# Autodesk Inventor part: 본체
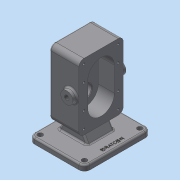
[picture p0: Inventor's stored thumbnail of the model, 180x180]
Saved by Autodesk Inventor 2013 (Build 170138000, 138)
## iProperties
Created: 2020-04
Part Number: 본체
Material: 일반
Document SubType Name: Modeling
Designer: dgall
Density: 1 g/cm^3
Author: dgall
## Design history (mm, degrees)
sketch "스케치1"
  geometry: L1 (-50, 60)-(50, 60); L2 (50, 60)-(50, -60); L3 (50, -60)-(-50, -60); L4 (-50, -60)-(-50, 60); 3 further points
  constraints: 8 end point, 2 midpoint, 2 parallel, 1 horizontal, 1 horizontal alignment, 1 perpendicular, 1 vertical alignment
  dimensions: "d0" = 100 distance of L1.start L1.end; "d2" = 120 distance of L1.end L2.end
extrude "돌출1" new body sketch "스케치1" stored distance "d3" = 10; taper "d4" = 0 deg
node "작업 평면1"
sketch "스케치2"
  geometry: L1 (145, -20)-(25, -20); L2 (25, -20)-(25, -100); L3 (25, -100)-(145, -100); L4 (145, -100)-(145, -20); L5 (-5, -120)-(-5, 0) reference; 2 further points
  constraints: 8 end point, 2 parallel, 1 horizontal, 1 horizontal alignment, 1 midpoint, 1 perpendicular
  dimensions: "d5" = 150 distance between parallel lines of L5 L4; "d6" = 80 distance of L3.end L1.start; "d7" = 120 distance of L1.start L1.end
extrude "돌출2" join sketch "스케치2" distance "d8" = 70; taper "d9" = 0 deg
extrude "돌출3" cut sketch "스케치2" distance "d10" = 17; taper "d11" = 0 deg
sketch "스케치3" dims "d31" = 10, "d38" = 10
  geometry: L1 (-25, -20)-(-145, -20) reference; L2 (-145, -20)-(-145, -100) reference; L3 (-145, -100)-(-25, -100) reference; L4 (-63, -84)-(-107, -84); L5 (-63, -36)-(-107, -36); A1 r 24 centre (-107, -60) between (-107, -36) and (-107, -84); A2 r 24 centre (-63, -60) between (-63, -84) and (-63, -36); 11 further points
  constraints: 4 end point, 4 point on circle, 3 horizontal, 2 centre point, 2 horizontal alignment, 2 midpoint, 2 parallel, 2 tangent, 1 equal radius, 1 vertical, 7 other
  dimensions: "d12" = 48 diameter of A1; "d14" = 44 distance of A2.centre A1.centre; "d15" = 9 distance from line of L2 point (-136, -91); "d16" = 9 distance from line of L3 point (-136, -91); "d17" = 29 horizontal distance of A1.centre point (-136, -91); "d20" = 62 distance of point (-136, -91) point (-136, -29); "d23" = 29 distance of point (-136, -91) point (-107, -91); "d28" = 44 distance of point (-107, -91) point (-63, -91); "d35" = 102 distance of point (-136, -91) point (-34, -91)
extrude "돌출4" cut sketch "스케치3" distance "d40" = 29; taper "d41" = 0 deg
hole "구멍1" sketch "스케치3" diameter "d42" = 4.134; stored, may be unused: countersink angle "d46" = 90 deg, drill point angle "d48" = 118 deg; dims "d43" = 10, "d44" = 4, "d45" = 2, "d47" = 12
sketch "스케치4"
  geometry: C1 r 19 at (-107, -60); A1 r 24 centre (-107, -60) between (-107, -36) and (-107, -84) reference; 1 further point
  constraints: 1 centre point, 1 coincident
  dimensions: "d49" = 38 diameter of C1
extrude "돌출5" join sketch "스케치4" distance "d51" = 41; taper "d52" = 0 deg
hole "구멍2" diameter "d55" = 28; stored, may be unused: countersink angle "d59" = 90 deg, drill point angle "d61" = 0 deg; dims "d53" = 10, "d54" = 10, "d56" = 10, "d57" = 28, "d58" = 7.3, "d60" = 7.3
sketch "스케치5"
  geometry: A1 r 24 centre (-107, -60) between (-107, -36) and (-107, -84) reference; 1 further point
hole "구멍3" sketch "스케치5" at (-107, -60) diameter "d62" = 17; stored, may be unused: countersink angle "d66" = 90 deg, drill point angle "d68" = 0 deg; dims "d63" = 10, "d64" = 25, "d65" = 15, "d67" = 50
sketch "스케치6"
  geometry: A1 r 24 centre (-63, -60) between (-63, -84) and (-63, -36) reference; 1 further point
hole "구멍4" sketch "스케치6" at (-63, -60) diameter "d69" = 25; stored, may be unused: countersink angle "d73" = 90 deg, drill point angle "d75" = 0 deg; dims "d70" = 10, "d71" = 25, "d72" = 15, "d74" = 15
sketch "스케치7"
  geometry: L1 (0, 120)-(0, 0) reference; L2 (-70, 150)-(30, 150) reference; C1 r 11 at (-14, 60); 1 further point
  constraints: 1 centre point
  dimensions: "d76" = 14 distance from line of L1 C1.centre; "d77" = 90 distance from line of L2 C1.centre; "d78" = 22 diameter of C1
extrude "돌출6" join sketch "스케치7" distance "d79" = 8; taper "d80" = 0 deg
sketch "스케치8"
  geometry: L1 (0, 120)-(0, 0) reference; L2 (30, -30)-(-70, -30) reference; C1 r 11 at (-14, 60); 1 further point
  constraints: 1 centre point
  dimensions: "d81" = 14 distance from line of L1 C1.centre; "d82" = 90 distance from line of L2 C1.centre; "d83" = 22 diameter of C1
extrude "돌출7" join sketch "스케치8" distance "d84" = 8; taper "d85" = 0 deg
hole "구멍5" diameter "d88" = 8.376; stored, may be unused: countersink angle "d92" = 90 deg, drill point angle "d94" = 0 deg; dims "d86" = 10, "d87" = 10, "d89" = 10, "d90" = 25, "d91" = 15, "d93" = 20
hole "구멍6" diameter "d97" = 8.376; stored, may be unused: countersink angle "d101" = 90 deg, drill point angle "d103" = 0 deg; dims "d95" = 10, "d96" = 10, "d98" = 10, "d99" = 25, "d100" = 15, "d102" = 20
sketch "스케치9"
  geometry: L1 (33, 25)-(-20, 25) reference; L2 (50, 5)-(-50, 5) reference; L3 (-20, 5)-(-8.453, 25); L4 (33, 5)-(21.453, 25); L5 (50, 5)-(50, -5) reference; 1 further point
  constraints: 4 end point, 4 point on line
  dimensions: "d104" = 53 distance of L4.start L3.start; "d105" = 17 distance from line of L5 L4.start; "d106" = 60 deg angle of L2 L3; "d107" = 60 deg angle of L2 L4
extrude "돌출8" join sketch "스케치9" stored distance "d108" = 48; taper "d109" = 0 deg
fillet "모깎기1" dims "d110" = 10
sketch "스케치10"
  geometry: A1 r 10 centre (-40, -50) between (-50, -50) and (-40, -60) reference; A2 r 10 centre (40, -50) between (40, -60) and (50, -50) reference; A3 r 10 centre (40, 50) between (50, 50) and (40, 60) reference; A4 r 10 centre (-40, 50) between (-40, 60) and (-50, 50) reference; 1 further point
hole "구멍7" sketch "스케치10" at (40, 50), (-40, 50), (-40, -50), (40, -50) diameter "d111" = 9; stored, may be unused: countersink angle "d115" = 90 deg, drill point angle "d117" = 0 deg; dims "d112" = 10, "d113" = 25, "d114" = 15, "d116" = 20
sketch "스케치11"
  geometry: L1 (-40, -60)-(40, -60) reference; L2 (50, -50)-(50, 50) reference; 2 further points
  constraints: 1 other
  dimensions: "d118" = 10 distance from line of L2 point (40, 0); "d119" = 60 distance from line of L1 point (40, 0)
feature "엠보싱1" sketch "스케치11" dims "d0" = 100, "d2" = 120, "d10" = 17, "d11" = 0, "d120" = 0.5, "d121" = 0
fillet "모깎기2" dims "d122" = 3
fillet "모깎기3" dims "d123" = 9
fillet "모깎기4" dims "d124" = 3
fillet "모깎기5" dims "d125" = 3
chamfer "모따기1" distance "d126" = 1; stored, may be unused: second distance "d127" = 2, angle "d128" = 45 deg
fillet "모깎기6" dims "d129" = 0.5
chamfer "모따기2" distance "d130" = 0.7; stored, may be unused: second distance "d131" = 2, angle "d132" = 30 deg
node "솔리드1"
